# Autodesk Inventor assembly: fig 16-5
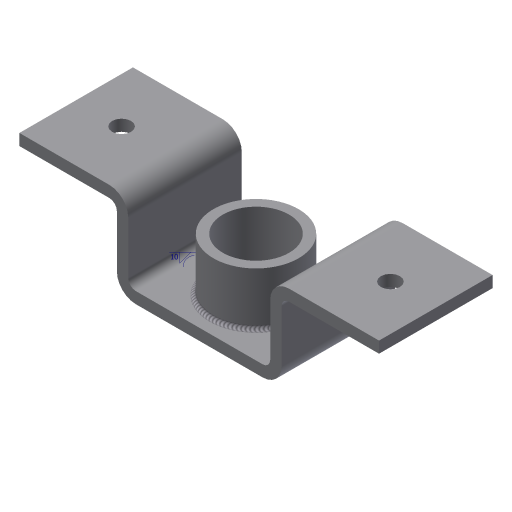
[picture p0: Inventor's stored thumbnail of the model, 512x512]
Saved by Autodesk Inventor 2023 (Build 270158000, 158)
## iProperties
Created: 2004-07
Part Number: fig 16-5
Document SubType Name: Weldment
Designer: CADCIM Technologies
Manufacturer: Standard
Standards Organization: Custom
Author: CADCIM Technologies
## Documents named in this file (3)
- D:\PROJECTS\Project 2022\Autodesk Inventor For Professional 2023\RESOURCES INVENTOR 2023\RESOURCES INVENTOR 2023\Inventor_2023_Part\Inventor_2023_Part\c16_Inv_2023_prt\fig 16-5\fig 16-5.iam
- D:\PROJECTS\Project 2022\Autodesk Inventor For Professional 2023\RESOURCES INVENTOR 2023\RESOURCES INVENTOR 2023\Inventor_2023_Part\Inventor_2023_Part\c16_Inv_2023_prt\fig 16-5\Bracket.ipt
- D:\PROJECTS\Project 2022\Autodesk Inventor For Professional 2023\RESOURCES INVENTOR 2023\RESOURCES INVENTOR 2023\Inventor_2023_Part\Inventor_2023_Part\c16_Inv_2023_prt\fig 16-5\cylinder.ipt
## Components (2 placed, 2 different names)
1. Bracket:1 — Insert:1
2. cylinder:1 — Insert:1
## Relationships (1: Insert 1)
- Insert:1: Bracket:1 ↔ cylinder:1
